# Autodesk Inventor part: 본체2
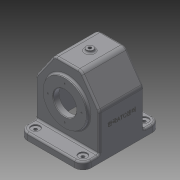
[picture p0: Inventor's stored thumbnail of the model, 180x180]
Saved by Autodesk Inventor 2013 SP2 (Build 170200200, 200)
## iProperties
Created: 2022-12
Part Number: 본체2
Material: Generic
Document SubType Name: Modeling
Designer: i
Density: 1 g/cm^3
Author: i
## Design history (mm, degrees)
sketch "스케치1"
  geometry: L1 (38.5, 55)-(-38.5, 55); L2 (-38.5, 55)-(-38.5, -55); L3 (-38.5, -55)-(38.5, -55); L4 (38.5, -55)-(38.5, 55); L5 (38.5, 55)-(-38.5, -55); L6 (-38.5, 55)-(38.5, -55); L7 (38.5, 55)-(83.5, 23.491); L8 (38.5, 55)-(93.435, 55); L9 (83.5, 23.491)-(83.5, -23.491); L10 (83.5, -23.491)-(38.5, -55); 1 further point
  constraints: 20 end point, 2 horizontal, 2 midpoint, 2 parallel, 2 perpendicular, 1 equal length
  dimensions: "d0" = 77 distance of L3.end L2.end; "d1" = 110 distance of L2.end L1.end; "d2" = 35 deg angle of L7 L8; "d4" = 125 deg angle of L9 L10; "d5" = 122 distance between parallel lines of L9 L2
extrude "돌출1" new body sketch "스케치1" stored distance "d6" = 77; taper "d7" = 0 deg
sketch "스케치2"
  geometry: L1 (-55, -38.5)-(55, -38.5) reference; C1 r 31 at (0, 26.5); 1 further point
  constraints: 1 centre point
  dimensions: "d8" = 62 diameter of C1; "d10" = 65 distance from line of C1.centre L1
extrude "돌출2" join sketch "스케치2" distance "d11" = 10; taper "d12" = 0 deg
sketch "스케치3"
  geometry: C1 r 31 at (0, 0) reference; C2 r 20 at (0, 0); 1 further point
  constraints: 1 centre point, 1 coincident
  dimensions: "d13" = 40 diameter of C2
extrude "돌출3" cut sketch "스케치3" stored distance "d14" = 15; taper "d15" = 0 deg
sketch "스케치4"
  geometry: L1 (-55, -38.5)-(55, -38.5) reference; C1 r 37.5 at (0, 26.5); 1 further point
  constraints: 1 centre point
  dimensions: "d16" = 75 diameter of C1; "d17" = 65 distance from line of L1 C1.centre
extrude "돌출4" join sketch "스케치4" distance "d18" = 5; taper "d19" = 0 deg
sketch "스케치5"
  geometry: C1 r 37.5 at (0, 0) reference; C2 r 20 at (0, 0); 1 further point
  constraints: 1 centre point, 1 coincident
  dimensions: "d20" = 40 diameter of C2
extrude "돌출6" cut sketch "스케치5" stored distance "d23" = 24; taper "d24" = 0 deg
sketch "스케치6"
  geometry: L1 (0, 0)-(0, 26); C1 r 31 at (0, 0) reference; 2 further points
  constraints: 2 end point, 1 coincident, 1 vertical
  dimensions: "d25" = 26 distance of L1.start L1.end
hole "구멍1" sketch "스케치6" at (0, 26) diameter "d26" = 2.459; stored, may be unused: countersink angle "d30" = 90 deg, drill point angle "d32" = 118 deg; dims "d27" = 6, "d28" = 4, "d29" = 2, "d31" = 8
sketch "스케치7"
  geometry: L1 (0, 0)-(0, 29); C1 r 37.5 at (0, 0) reference; 2 further points
  constraints: 2 end point, 1 coincident, 1 vertical
  dimensions: "d36" = 29 distance of L1.start L1.end
hole "구멍2" sketch "스케치7" at (0, 29) diameter "d37" = 2.459; stored, may be unused: countersink angle "d41" = 90 deg, drill point angle "d43" = 118 deg; dims "d38" = 6, "d39" = 4, "d40" = 2, "d42" = 8
sketch "스케치8"
  geometry: L1 (0, 0)-(77, 0) reference; L2 (77, 110)-(77, 0) reference; L3 (0, 110)-(77, 110) reference; L4 (0, 0)-(0, 110) reference; L5 (-28.5, 110)-(105.5, 110); L6 (105.5, 110)-(105.5, 0); L7 (105.5, 0)-(-28.5, 0); L8 (-28.5, 0)-(-28.5, 110); L9 (-28.5, 110)-(105.5, 0); L10 (105.5, 110)-(-28.5, 0); 1 further point
  constraints: 12 end point, 2 midpoint, 2 parallel, 1 horizontal, 1 perpendicular
  dimensions: "d47" = 134 distance of L6.end L7.end; "d48" = 110 distance of L5.end L6.end
extrude "돌출7" join sketch "스케치8" distance "d49" = 12; taper "d50" = 0 deg
fillet "모깎기1" dims "d51" = 14
sketch "스케치9"
  geometry: L1 (91.5, 0)-(77, 0) reference; L2 (77, -110)-(77, 0) reference; L3 (77, -110)-(91.5, -110) reference; L4 (105.5, -96)-(105.5, -14) reference; A1 r 14 centre (-14.5, -14) between (-14.5, 0) and (-28.5, -14) reference; A2 r 14 centre (-14.5, -96) between (-28.5, -96) and (-14.5, -110) reference; A3 r 14 centre (91.5, -14) between (105.5, -14) and (91.5, 0) reference; A4 r 14 centre (91.5, -96) between (91.5, -110) and (105.5, -96) reference; 5 further points
  constraints: 4 coincident
hole "구멍3" sketch "스케치9" at (-14.5, -14), (91.5, -14), (91.5, -96), (-14.5, -96) diameter "d52" = 5.5; stored, may be unused: countersink angle "d56" = 90 deg, drill point angle "d58" = 118 deg; dims "d53" = 6, "d54" = 15, "d55" = 2, "d57" = 8
sketch "스케치12"
  geometry: C1 r 6 at (38.5, 23.491); 1 further point
  constraints: 1 centre point, 1 coincident
  dimensions: "d69" = 12 diameter of C1
extrude "돌출10" join sketch "스케치12" distance "d70" = 4; taper "d71" = 0 deg
sketch "스케치13"
  geometry: C1 r 6 at (0, 0) reference; 1 further point
  constraints: 1 coincident
hole "구멍4" sketch "스케치13" at (0, 0) diameter "d72" = 5.188; stored, may be unused: countersink angle "d76" = 90 deg, drill point angle "d78" = 118 deg; dims "d73" = 12, "d74" = 15, "d75" = 2, "d77" = 8
sketch "스케치14"
  geometry: L1 (-100.5, 91)-(-33.5, 91); L2 (-33.5, 91)-(-33.5, -9); L3 (-33.5, -9)-(-100.5, -9); L4 (-100.5, -9)-(-100.5, 91); L5 (-100.5, 91)-(-33.5, -9); L6 (-33.5, 91)-(-100.5, -9); C1 r 2.594 at (-67, 41) reference
  constraints: 12 end point, 2 midpoint, 2 parallel, 1 horizontal, 1 perpendicular
  dimensions: "d80" = 67 distance of L2.end L3.end; "d81" = 100 distance of L1.end L2.end
extrude "돌출11" cut sketch "스케치14" distance "d82" = 77; taper "d83" = 0 deg
feature "쉘2" dims "d79" = 5
fillet "모깎기2" dims "d84" = 10
fillet "모깎기3" dims "d85" = 3
chamfer "모따기1" distance "d86" = 1; stored, may be unused: second distance "d87" = 2, angle "d88" = 45 deg
fillet "모깎기4" dims "d89" = 3
sketch "스케치15"
  geometry: L1 (0, 0)-(106, 0) reference; L2 (14.5, 73.847)-(14.5, 15) reference; 2 further points
  constraints: 1 other
  dimensions: "d90" = 50 distance from line of L1 point (53, 50); "d91" = 38.5 distance from line of point (53, 50) L2
feature "엠보싱1" sketch "스케치15" dims "d0" = 77, "d1" = 110, "d2" = 35 deg, "d4" = 125 deg, "d5" = 122, "d13" = 40, "d92" = 0.5, "d93" = 0
node "솔리드1"
pattern_circular "원형 패턴1" dims angle "d34" = 360 deg
pattern_circular "원형 패턴2" dims angle "d45" = 360 deg
node "투영된 루프1"
